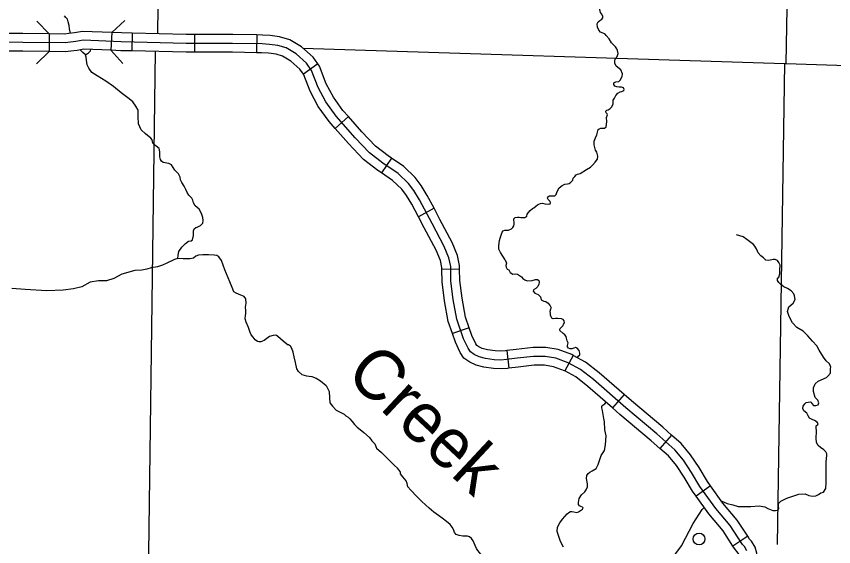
# Model space of a CAD drawing. Extents: x 1369979 to 1371646, y 379997 to 381064.
# Drawn here: x 1370592.6 to 1370673.6, y 380189.4 to 380241.9 of the extents above; entities that cross this region are included whole.
import ezdxf

# ---------------------------------------------------------------- set-up
doc = ezdxf.new("R2010")
doc.units = 0
doc.layers.add('R_Border Notes', color=7, linetype='Continuous')

msp = doc.modelspace()

# ---------------------------------------------------------------- linework, layer by layer
at = {"layer": 'R_Border Notes'}
for p, q in [((1370604.087, 380240.247), (1370604.044, 380238.489)), ((1370610.252, 380240.117), (1370610.252, 380238.359)), ((1370616.454, 380240.074), (1370616.423, 380238.316)), ((1370622.485, 380237.214), (1370621.054, 380236.193)), ((1370625.518, 380231.985), (1370624.205, 380230.817)), ((1370629.795, 380227.863), (1370628.813, 380226.405)), ((1370634.006, 380222.902), (1370632.455, 380222.075)), ((1370636.545, 380216.871), (1370634.787, 380216.839)), ((1370637.487, 380211.071), (1370635.828, 380210.489)), ((1370641.21, 380208.808), (1370641.428, 380207.064)), ((1370647.801, 380208.334), (1370646.963, 380206.789)), ((1370652.845, 380204.465), (1370651.691, 380203.139)), ((1370657.556, 380200.444), (1370656.392, 380199.127)), ((1370661.419, 380195.407), (1370659.988, 380194.386)), ((1370665.116, 380190.412), (1370663.645, 380189.449))]:
    msp.add_line(p, q, dxfattribs=at)
for points in [[(1370607.61, 380300.722), (1370606.969, 380269.654), (1370606.596, 380240.186)], [(1370670.024, 380299.56), (1370668.871, 380237.248)], [(1370650.198, 380241.187), (1370650.272, 380241.375), (1370650.455, 380241.522), (1370650.632, 380241.632), (1370650.749, 380241.787), (1370650.749, 380241.949), (1370650.61, 380242.177), (1370650.514, 380242.302), (1370650.367, 380242.869), (1370650.33, 380243.163), (1370650.316, 380243.487), (1370650.176, 380244.546)], [(1370597.953, 380240.24), (1370597.88, 380240.679), (1370597.843, 380241.01), (1370597.733, 380241.371), (1370597.682, 380241.628), (1370597.52, 380241.79), (1370597.358, 380241.974)], [(1370594.625, 380241.443), (1370595.856, 380240.189)], [(1370602.058, 380240.312), (1370603.36, 380241.494)], [(1370651.609, 380239.304), (1370651.359, 380239.694), (1370651.087, 380240.032), (1370650.977, 380240.143), (1370650.838, 380240.223), (1370650.668, 380240.282), (1370650.529, 380240.363), (1370650.352, 380240.54), (1370650.213, 380240.834), (1370650.198, 380241.187)], [(1370595.856, 380240.189), (1370593.247, 380240.221), (1370591.723, 380240.236)], [(1370595.856, 380240.189), (1370595.839, 380238.431)], [(1370597.791, 380240.22), (1370597.379, 380240.17), (1370595.856, 380240.189)], [(1370602.058, 380240.312), (1370599.152, 380240.433), (1370598.363, 380240.29), (1370597.791, 380240.22)], [(1370602.058, 380240.312), (1370601.974, 380238.556)], [(1370604.087, 380240.247), (1370603.015, 380240.273), (1370602.058, 380240.312)], [(1370610.252, 380240.117), (1370609.446, 380240.117), (1370604.087, 380240.247)], [(1370616.454, 380240.074), (1370614.05, 380240.117), (1370610.252, 380240.117)], [(1370622.485, 380237.214), (1370622.014, 380237.873), (1370620.866, 380238.905), (1370619.704, 380239.609), (1370618.693, 380239.893), (1370617.771, 380240.009), (1370616.996, 380240.064), (1370616.454, 380240.074)], [(1370599.213, 380239.55), (1370598.495, 380239.42), (1370597.427, 380239.29), (1370593.237, 380239.342), (1370587.98, 380239.394), (1370583.348, 380239.394), (1370576.087, 380239.316), (1370571.533, 380239.29)], [(1370665.035, 380188.98), (1370664.775, 380189.397), (1370664.593, 380189.606), (1370663.37, 380191.473), (1370661.938, 380193.167), (1370660.377, 380195.355), (1370659.544, 380196.746), (1370658.737, 380197.971), (1370657.879, 380198.987), (1370656.109, 380200.55), (1370653.012, 380203.155), (1370649.811, 380205.942), (1370648.543, 380206.932), (1370647.294, 380207.609), (1370646.097, 380208.052), (1370645.03, 380208.235), (1370643.885, 380208.235), (1370642.245, 380208.052), (1370641.204, 380207.922), (1370640.632, 380207.87), (1370639.981, 380207.896), (1370639.122, 380208.026), (1370638.498, 380208.182), (1370638.003, 380208.417), (1370637.613, 380208.677), (1370637.379, 380209.047), (1370636.936, 380209.985), (1370636.259, 380211.913), (1370635.921, 380213.867), (1370635.687, 380215.69), (1370635.661, 380217.149), (1370635.479, 380217.983), (1370635.01, 380219.129), (1370633.813, 380221.396), (1370632.564, 380223.74), (1370631.991, 380224.665), (1370631.471, 380225.368), (1370630.456, 380226.358), (1370628.946, 380227.374), (1370627.601, 380228.39), (1370626.196, 380229.901), (1370624.296, 380232.037), (1370623.281, 380233.455), (1370622.526, 380234.861), (1370621.875, 380236.555), (1370621.355, 380237.284), (1370620.34, 380238.196), (1370619.351, 380238.795), (1370618.518, 380239.029), (1370617.685, 380239.134), (1370616.957, 380239.186), (1370614.042, 380239.238), (1370609.435, 380239.238), (1370602.986, 380239.394), (1370599.213, 380239.55)], [(1370651.98, 380237.668), (1370652.102, 380237.825), (1370652.205, 380238.038), (1370652.264, 380238.252), (1370652.212, 380238.531), (1370652.124, 380238.7), (1370651.984, 380238.906), (1370651.793, 380239.083), (1370651.609, 380239.304), (1370651.543, 380239.399)], [(1370595.834, 380238.431), (1370593.228, 380238.463), (1370591.706, 380238.478)], [(1370595.839, 380238.431), (1370594.584, 380237.2)], [(1370595.839, 380238.431), (1370595.834, 380238.431)], [(1370598.004, 380238.475), (1370597.475, 380238.41), (1370595.839, 380238.431)], [(1370601.974, 380238.556), (1370599.274, 380238.668), (1370598.626, 380238.551), (1370598.004, 380238.475)], [(1370603.795, 380233.744), (1370602.982, 380234.335), (1370602.217, 380234.983), (1370601.46, 380235.505), (1370600.615, 380236.028), (1370600.093, 380236.344), (1370599.784, 380236.771), (1370599.608, 380237.117), (1370599.564, 380237.565), (1370599.519, 380237.882), (1370599.453, 380238.099), (1370599.203, 380238.342), (1370599.056, 380238.481), (1370598.923, 380238.605)], [(1370599.453, 380238.099), (1370599.762, 380238.295), (1370599.946, 380238.487), (1370599.968, 380238.64)], [(1370604.044, 380238.489), (1370602.958, 380238.516), (1370601.974, 380238.556)], [(1370603.156, 380237.255), (1370601.974, 380238.556)], [(1370610.252, 380238.359), (1370609.425, 380238.359), (1370604.044, 380238.489)], [(1370606.377, 380238.433), (1370605.559, 380178.814)], [(1370616.423, 380238.316), (1370614.034, 380238.359), (1370610.252, 380238.359)], [(1370621.054, 380236.193), (1370620.696, 380236.695), (1370619.814, 380237.487), (1370618.998, 380237.981), (1370618.344, 380238.166), (1370617.599, 380238.259), (1370616.917, 380238.307), (1370616.423, 380238.316)], [(1370621.017, 380238.769), (1370668.758, 380237.252), (1370668.871, 380237.248), (1370730.521, 380235.229), (1370730.683, 380235.223), (1370792.292, 380234.546), (1370792.765, 380234.537), (1370854.39, 380233.44), (1370854.696, 380233.431), (1370866.771, 380233.075)], [(1370652.024, 380234.073), (1370652.23, 380234.32), (1370652.472, 380234.446), (1370652.619, 380234.482), (1370652.81, 380234.578), (1370652.869, 380234.688), (1370652.781, 380234.85), (1370652.59, 380234.902), (1370652.362, 380234.909), (1370652.119, 380234.931), (1370651.921, 380235.012), (1370651.833, 380235.181), (1370651.848, 380235.328), (1370652.017, 380235.424), (1370652.325, 380235.461), (1370652.472, 380235.608), (1370652.656, 380235.954), (1370652.685, 380236.226), (1370652.538, 380236.616), (1370652.072, 380236.997), (1370651.921, 380237.293), (1370651.936, 380237.528), (1370651.98, 380237.668)], [(1370625.518, 380231.985), (1370624.983, 380232.587), (1370624.028, 380233.92), (1370623.327, 380235.228), (1370622.656, 380236.974), (1370622.485, 380237.214)], [(1370668.758, 380237.252), (1370668.017, 380189.594)], [(1370624.205, 380230.817), (1370623.608, 380231.488), (1370622.533, 380232.989), (1370621.725, 380234.494), (1370621.095, 380236.135), (1370621.054, 380236.193)], [(1370605.926, 380229.851), (1370605.397, 380230.272), (1370604.971, 380230.676), (1370604.714, 380231.265), (1370604.677, 380232.001), (1370604.677, 380232.633), (1370604.449, 380233.038), (1370604.14, 380233.443), (1370603.795, 380233.744)], [(1370651.215, 380232.169), (1370651.179, 380232.263), (1370651.076, 380232.374), (1370651.039, 380232.433), (1370651.032, 380232.513), (1370651.142, 380232.624), (1370651.274, 380232.661), (1370651.473, 380232.793), (1370651.649, 380232.955), (1370651.774, 380233.257), (1370651.781, 380233.396), (1370651.781, 380233.617), (1370651.906, 380233.823), (1370652.024, 380234.073)], [(1370629.795, 380227.863), (1370629.457, 380228.09), (1370628.192, 380229.045), (1370626.846, 380230.493), (1370625.518, 380231.985)], [(1370649.892, 380229.553), (1370650.002, 380229.899), (1370650.157, 380230.186), (1370650.289, 380230.708), (1370650.377, 380230.774), (1370650.546, 380230.826), (1370650.679, 380230.826), (1370650.921, 380230.855), (1370651.061, 380230.988), (1370651.112, 380231.201), (1370651.134, 380231.51), (1370651.12, 380231.885), (1370651.215, 380232.169)], [(1370628.813, 380226.405), (1370628.436, 380226.658), (1370627.01, 380227.735), (1370625.545, 380229.31), (1370624.205, 380230.817)], [(1370607.97, 380227.198), (1370607.72, 380227.334), (1370607.169, 380227.437), (1370606.985, 380227.57), (1370606.875, 380227.732), (1370606.831, 380228.004), (1370606.831, 380228.497), (1370606.772, 380228.813), (1370606.456, 380229.049), (1370606.301, 380229.181), (1370606.132, 380229.373), (1370606.051, 380229.674), (1370605.926, 380229.851)], [(1370650.002, 380228.673), (1370649.892, 380229.207), (1370649.892, 380229.553)], [(1370649.708, 380227.176), (1370649.973, 380227.466), (1370650.208, 380227.783), (1370650.238, 380228.062), (1370650.135, 380228.459), (1370650.002, 380228.673)], [(1370634.006, 380222.902), (1370633.326, 380224.179), (1370632.72, 380225.159), (1370632.135, 380225.948), (1370631.013, 380227.043), (1370629.795, 380227.863)], [(1370610.734, 380222.826), (1370610.337, 380223.137), (1370610.175, 380223.453), (1370610.109, 380223.711), (1370609.984, 380223.924), (1370609.712, 380224.204), (1370609.543, 380224.461), (1370609.389, 380224.756), (1370609.234, 380225.094), (1370608.992, 380225.462), (1370608.867, 380225.727), (1370608.845, 380225.977), (1370608.668, 380226.33), (1370608.315, 380226.669), (1370607.97, 380227.198)], [(1370644.991, 380223.347), (1370645.371, 380223.313), (1370645.511, 380223.357), (1370645.548, 380223.453), (1370645.518, 380223.592), (1370645.32, 380223.784), (1370645.247, 380223.894), (1370645.291, 380224.041), (1370645.452, 380224.129), (1370645.688, 380224.129), (1370645.79, 380224.144), (1370645.982, 380224.152), (1370646.107, 380224.277), (1370646.232, 380224.578), (1370646.408, 380224.939), (1370646.709, 380225.174), (1370646.967, 380225.292), (1370647.239, 380225.314), (1370647.415, 380225.351), (1370647.569, 380225.498), (1370647.76, 380225.697), (1370647.819, 380225.895), (1370647.959, 380226.065), (1370648.106, 380226.204), (1370648.246, 380226.285), (1370648.496, 380226.337), (1370649.113, 380226.764), (1370649.51, 380226.97), (1370649.708, 380227.176)], [(1370632.455, 380222.075), (1370631.802, 380223.302), (1370631.263, 380224.171), (1370630.807, 380224.789), (1370629.899, 380225.674), (1370628.813, 380226.405)], [(1370636.545, 380216.871), (1370636.538, 380217.252), (1370636.321, 380218.245), (1370635.808, 380219.501), (1370634.59, 380221.807), (1370634.006, 380222.902)], [(1370641.381, 380220.755), (1370641.705, 380220.883), (1370641.815, 380221.008), (1370641.911, 380221.155), (1370641.97, 380221.317), (1370641.955, 380221.53), (1370641.911, 380221.714), (1370641.933, 380221.846), (1370642.065, 380221.979), (1370642.278, 380222.023), (1370642.433, 380222.016), (1370642.631, 380221.994), (1370642.83, 380221.986), (1370643.021, 380222.001), (1370643.197, 380222.119), (1370643.241, 380222.317), (1370643.359, 380222.487), (1370643.535, 380222.7), (1370643.763, 380222.884), (1370643.895, 380222.965), (1370644.087, 380223.112), (1370644.278, 380223.237), (1370644.41, 380223.318), (1370644.557, 380223.392), (1370644.755, 380223.414), (1370644.991, 380223.347)], [(1370608.61, 380217.931), (1370608.639, 380218.265), (1370608.698, 380218.625), (1370609.006, 380219.067), (1370609.367, 380219.42), (1370609.668, 380219.655), (1370609.947, 380219.692), (1370610.05, 380219.788), (1370610.146, 380220.2), (1370610.168, 380220.509), (1370610.153, 380220.671), (1370610.219, 380220.869), (1370610.396, 380220.994), (1370610.528, 380221.046), (1370610.866, 380221.193), (1370611.094, 380221.421), (1370611.116, 380221.701), (1370611.087, 380221.98), (1370610.962, 380222.378), (1370610.734, 380222.826)], [(1370634.787, 380216.839), (1370634.784, 380217.047), (1370634.636, 380217.721), (1370634.213, 380218.757), (1370633.037, 380220.984), (1370632.455, 380222.075)], [(1370641.064, 380217.793), (1370640.838, 380218.172), (1370640.602, 380218.533), (1370640.448, 380218.849), (1370640.441, 380219.209), (1370640.499, 380219.717), (1370640.558, 380219.938), (1370640.749, 380220.549), (1370640.874, 380220.666), (1370641.029, 380220.74), (1370641.381, 380220.755)], [(1370668.184, 380216.096), (1370668.304, 380216.399), (1370668.304, 380216.782), (1370668.319, 380217.267), (1370668.202, 380217.547), (1370668.055, 380217.724), (1370667.834, 380217.827), (1370667.628, 380217.841), (1370667.202, 380217.738), (1370666.908, 380217.768), (1370666.673, 380217.988), (1370666.408, 380218.194), (1370666.143, 380218.504), (1370666.011, 380218.827), (1370665.82, 380219.151), (1370665.673, 380219.328), (1370665.423, 380219.519), (1370665.026, 380219.813), (1370664.658, 380220.078), (1370664.012, 380220.284)], [(1370613.268, 380216.798), (1370612.937, 380217.74), (1370612.672, 380218.086), (1370612.481, 380218.218), (1370612.195, 380218.255), (1370611.665, 380218.306), (1370611.077, 380218.292), (1370610.673, 380218.262), (1370610.401, 380218.159), (1370610.158, 380217.975), (1370609.813, 380217.902), (1370609.137, 380217.902), (1370608.61, 380217.931), (1370608.279, 380217.828), (1370607.522, 380217.475), (1370607.103, 380217.269), (1370606.595, 380217.1), (1370605.963, 380216.997), (1370605.544, 380216.879), (1370605.044, 380216.769), (1370604.346, 380216.732)], [(1370641.064, 380217.793), (1370641.189, 380217.484), (1370641.123, 380217.234), (1370641.145, 380217.072), (1370641.255, 380216.866), (1370641.409, 380216.8), (1370641.564, 380216.542), (1370641.806, 380216.395), (1370642.078, 380216.403), (1370642.292, 380216.373), (1370642.688, 380216.123), (1370642.799, 380215.954), (1370642.997, 380215.814), (1370643.254, 380215.733), (1370643.747, 380215.755), (1370644.063, 380215.858), (1370644.262, 380215.858), (1370644.401, 380215.755), (1370644.423, 380215.571), (1370644.401, 380215.402), (1370644.313, 380215.174), (1370644.092, 380214.953), (1370643.857, 380214.828), (1370643.835, 380214.703), (1370644.004, 380214.512), (1370644.342, 380214.379), (1370644.57, 380214.144), (1370644.636, 380213.835)], [(1370604.346, 380216.732), (1370603.048, 380216.381), (1370602.257, 380215.963), (1370601.522, 380215.718), (1370600.748, 380215.735), (1370599.928, 380215.591), (1370599.093, 380215.137), (1370598.265, 380214.943), (1370597.247, 380214.781), (1370595.606, 380214.738), (1370593.489, 380214.853), (1370592.136, 380214.968)], [(1370615.377, 380211.611), (1370615.275, 380211.969), (1370615.333, 380212.271), (1370615.348, 380212.455), (1370615.363, 380212.771), (1370615.326, 380213.102), (1370615.377, 380213.5), (1370615.341, 380213.941), (1370615.179, 380214.184), (1370614.87, 380214.309), (1370614.385, 380214.486), (1370614.15, 380214.642), (1370613.988, 380215.047), (1370613.76, 380215.606), (1370613.268, 380216.798)], [(1370635.828, 380210.488), (1370635.406, 380211.691), (1370635.052, 380213.736), (1370634.809, 380215.626), (1370634.787, 380216.839)], [(1370637.487, 380211.071), (1370637.113, 380212.135), (1370636.79, 380213.998), (1370636.565, 380215.754), (1370636.545, 380216.871)], [(1370670.61, 380210.719), (1370669.963, 380211.108), (1370669.536, 380211.549), (1370669.228, 380212.182), (1370669.066, 380212.682), (1370669.184, 380213.138), (1370669.625, 380213.506), (1370669.801, 380213.859), (1370669.757, 380214.227), (1370669.669, 380214.448), (1370669.419, 380214.742), (1370669.066, 380214.948), (1370668.698, 380215.14), (1370668.346, 380215.404), (1370668.199, 380215.566), (1370668.052, 380215.743), (1370668.052, 380215.875), (1370668.066, 380215.978), (1370668.184, 380216.096)], [(1370644.636, 380213.835), (1370644.901, 380213.698), (1370645.092, 380213.683), (1370645.335, 380213.514), (1370645.511, 380213.256), (1370645.607, 380213.058), (1370645.57, 380212.903), (1370645.474, 380212.675), (1370645.518, 380212.513), (1370645.526, 380212.366)], [(1370618.383, 380210.308), (1370618.243, 380210.33), (1370618.052, 380210.308), (1370617.685, 380210.191), (1370617.178, 380209.801), (1370616.832, 380209.661), (1370616.648, 380209.668), (1370616.501, 380209.72), (1370616.288, 380209.867), (1370616.082, 380210.124), (1370615.891, 380210.382), (1370615.796, 380210.617), (1370615.605, 380211.088), (1370615.377, 380211.611)], [(1370646.803, 380210.511), (1370646.487, 380210.787), (1370646.479, 380210.868), (1370646.523, 380211.001), (1370646.714, 380211.207), (1370646.825, 380211.31), (1370646.861, 380211.413), (1370646.935, 380211.552), (1370646.913, 380211.758), (1370646.803, 380211.891), (1370646.656, 380211.95), (1370646.273, 380211.987), (1370646.06, 380211.972), (1370645.825, 380211.957), (1370645.678, 380212.031), (1370645.612, 380212.148), (1370645.56, 380212.318)], [(1370641.21, 380208.808), (1370641.11, 380208.796), (1370640.609, 380208.75), (1370640.065, 380208.772), (1370639.295, 380208.889), (1370638.795, 380209.014), (1370638.438, 380209.184), (1370638.256, 380209.305), (1370638.15, 380209.472), (1370637.75, 380210.319), (1370637.487, 380211.071)], [(1370619.533, 380209.363), (1370619.42, 380209.462), (1370619.052, 380209.756), (1370618.795, 380209.962), (1370618.523, 380210.213), (1370618.383, 380210.308)], [(1370641.428, 380207.064), (1370641.299, 380207.048), (1370640.654, 380206.989), (1370639.897, 380207.02), (1370638.949, 380207.163), (1370638.2, 380207.351), (1370637.569, 380207.65), (1370636.97, 380208.05), (1370636.607, 380208.623), (1370636.122, 380209.651), (1370635.828, 380210.488)], [(1370648.178, 380208.13), (1370648.273, 380208.208), (1370648.449, 380208.399), (1370648.457, 380208.568), (1370648.383, 380208.818), (1370648.185, 380209.046), (1370648.067, 380209.127), (1370648.023, 380209.127), (1370647.854, 380209.046), (1370647.67, 380208.973), (1370647.501, 380208.98), (1370647.339, 380209.046), (1370647.244, 380209.179), (1370647.251, 380209.311), (1370647.295, 380209.569), (1370647.207, 380209.768), (1370647.163, 380209.907), (1370647.156, 380210.04), (1370647.097, 380210.194), (1370646.972, 380210.356), (1370646.803, 380210.511)], [(1370672.095, 380205.767), (1370672.903, 380206.143), (1370673.05, 380206.275), (1370673.315, 380206.569), (1370673.329, 380206.746), (1370673.3, 380207.04), (1370673.344, 380207.173), (1370673.212, 380207.482), (1370672.888, 380207.805), (1370672.609, 380208.173), (1370672.197, 380208.85), (1370671.948, 380209.277), (1370671.521, 380209.733), (1370671.065, 380210.263), (1370670.771, 380210.572), (1370670.61, 380210.719)], [(1370620.138, 380208.181), (1370620.044, 380208.668), (1370619.897, 380209.028), (1370619.765, 380209.234), (1370619.567, 380209.396), (1370619.42, 380209.462)], [(1370647.801, 380208.334), (1370647.658, 380208.412), (1370646.325, 380208.905), (1370645.105, 380209.113), (1370643.836, 380209.113), (1370642.142, 380208.925), (1370641.21, 380208.808)], [(1370652.845, 380204.465), (1370650.37, 380206.62), (1370649.027, 380207.67), (1370647.801, 380208.334)], [(1370620.265, 380207.623), (1370620.138, 380208.181)], [(1370620.919, 380206.453), (1370620.581, 380206.74), (1370620.397, 380207.012), (1370620.265, 380207.623)], [(1370646.963, 380206.789), (1370646.93, 380206.807), (1370645.869, 380207.2), (1370644.955, 380207.356), (1370643.934, 380207.356), (1370642.348, 380207.179), (1370641.428, 380207.064)], [(1370651.691, 380203.139), (1370649.251, 380205.264), (1370648.06, 380206.194), (1370646.963, 380206.789)], [(1370620.919, 380206.453), (1370621.372, 380206.304), (1370621.879, 380206.245), (1370622.313, 380206.083), (1370622.769, 380205.811), (1370623.311, 380205.363), (1370623.598, 380204.767), (1370623.639, 380204.13), (1370623.665, 380203.618), (1370623.937, 380203.302), (1370624.32, 380202.919), (1370624.82, 380202.639), (1370625.092, 380202.522), (1370625.268, 380202.358), (1370625.511, 380202.226), (1370625.658, 380202.057), (1370625.891, 380201.799), (1370626.127, 380201.498), (1370626.391, 380201.218), (1370626.693, 380200.99), (1370627.045, 380200.703), (1370627.603, 380200.213), (1370627.839, 380199.882), (1370628.126, 380199.57)], [(1370671.903, 380201.372), (1370672.05, 380201.5), (1370672.08, 380201.603), (1370671.977, 380201.735), (1370671.742, 380201.897), (1370671.506, 380201.986), (1370671.242, 380202.103), (1370671.11, 380202.339), (1370670.977, 380202.618), (1370670.668, 380202.839), (1370670.566, 380203.06), (1370670.61, 380203.295), (1370670.757, 380203.545), (1370670.918, 380203.663), (1370671.286, 380203.737), (1370671.404, 380203.693), (1370671.477, 380203.575), (1370671.639, 380203.369), (1370671.859, 380203.369), (1370672.095, 380203.442), (1370672.153, 380203.619), (1370672.05, 380203.913), (1370671.786, 380204.178), (1370671.624, 380204.767), (1370671.624, 380205.105), (1370671.8, 380205.502), (1370672.095, 380205.767)], [(1370657.556, 380200.444), (1370656.683, 380201.215), (1370653.583, 380203.822), (1370652.845, 380204.465)], [(1370650.897, 380201.768), (1370650.831, 380202.072), (1370650.765, 380202.492), (1370650.721, 380202.889), (1370650.654, 380203.146), (1370650.654, 380203.271), (1370650.75, 380203.397), (1370650.956, 380203.551), (1370651.066, 380203.684)], [(1370656.392, 380199.127), (1370655.535, 380199.884), (1370652.44, 380202.487), (1370651.691, 380203.139)], [(1370650.295, 380197.513), (1370650.574, 380198.42), (1370650.897, 380198.92), (1370651, 380199.479), (1370651.059, 380200.355), (1370650.956, 380200.944), (1370650.897, 380201.768)], [(1370672.627, 380194.772), (1370672.859, 380195.162), (1370672.874, 380195.736), (1370672.874, 380196.913), (1370672.874, 380197.796), (1370672.947, 380198.429), (1370672.947, 380198.576), (1370672.859, 380198.782), (1370672.638, 380198.988), (1370672.315, 380199.194), (1370672.095, 380199.4), (1370671.933, 380199.709), (1370671.903, 380200.136), (1370671.918, 380200.783), (1370671.889, 380201.225), (1370671.903, 380201.372)], [(1370661.419, 380195.407), (1370661.113, 380195.837), (1370660.288, 380197.214), (1370659.442, 380198.498), (1370658.508, 380199.603), (1370657.556, 380200.444)], [(1370628.126, 380199.57), (1370628.316, 380199.139), (1370628.808, 380198.712), (1370629.631, 380197.873), (1370630.087, 380197.424), (1370630.378, 380197.151)], [(1370659.988, 380194.386), (1370659.641, 380194.873), (1370658.8, 380196.278), (1370658.032, 380197.443), (1370657.249, 380198.37), (1370656.392, 380199.127)], [(1370632.796, 380193.852), (1370632.311, 380194.363), (1370631.709, 380194.988), (1370631.415, 380195.326), (1370631.334, 380195.643), (1370631.238, 380195.922), (1370630.929, 380196.312), (1370630.679, 380196.614), (1370630.672, 380196.724), (1370630.643, 380196.827), (1370630.554, 380196.967), (1370630.378, 380197.151)], [(1370648.546, 380192.98), (1370648.744, 380193.114), (1370648.781, 380193.217), (1370648.722, 380193.298), (1370648.56, 380193.371), (1370648.435, 380193.415), (1370648.347, 380193.555), (1370648.318, 380193.768), (1370648.413, 380194.173), (1370648.634, 380194.534), (1370648.95, 380194.806), (1370649.09, 380195.012), (1370649.214, 380195.328), (1370649.222, 380195.608), (1370649.134, 380196.123), (1370649.163, 380196.432), (1370649.288, 380196.638), (1370649.442, 380196.778), (1370649.692, 380196.903), (1370650.067, 380197.138), (1370650.295, 380197.513)], [(1370665.116, 380190.412), (1370664.076, 380192), (1370662.633, 380193.707), (1370661.419, 380195.407)], [(1370665.411, 380193.38), (1370666.246, 380193.418), (1370666.79, 380193.33), (1370667.099, 380193.183), (1370667.613, 380192.977), (1370667.863, 380192.962), (1370668.099, 380192.992), (1370668.187, 380193.153), (1370668.172, 380193.389), (1370668.157, 380193.654), (1370668.378, 380193.904), (1370668.981, 380194.183), (1370670.172, 380194.581), (1370670.789, 380194.61), (1370671.157, 380194.463), (1370671.539, 380194.375), (1370671.848, 380194.419), (1370672.112, 380194.551), (1370672.362, 380194.713), (1370672.627, 380194.772)], [(1370637.903, 380189.972), (1370637.714, 380190.181), (1370637.538, 380190.357), (1370637.317, 380190.416), (1370636.861, 380190.416), (1370636.509, 380190.504), (1370636.193, 380190.607), (1370636.038, 380190.791), (1370635.965, 380191.005), (1370635.796, 380191.321), (1370635.604, 380191.586), (1370635.259, 380191.865), (1370634.811, 380192.211), (1370634.458, 380192.484), (1370633.995, 380192.793), (1370633.524, 380193.197), (1370632.796, 380193.852)], [(1370663.645, 380189.449), (1370662.664, 380190.947), (1370661.244, 380192.627), (1370659.988, 380194.386)], [(1370662.485, 380193.915), (1370663.074, 380193.674), (1370663.618, 380193.527), (1370664.162, 380193.38), (1370664.823, 380193.365), (1370665.411, 380193.38)], [(1370646.83, 380189.33), (1370646.561, 380189.904), (1370646.208, 380190.89), (1370646.259, 380191.332), (1370646.465, 380191.751), (1370646.752, 380192.104), (1370647.193, 380192.641), (1370647.362, 380192.774), (1370647.531, 380192.877), (1370647.656, 380192.884), (1370647.869, 380192.825), (1370648.156, 380192.781), (1370648.318, 380192.825), (1370648.546, 380192.98)], [(1370656.814, 380186.945), (1370657.428, 380187.965), (1370658.546, 380189.466), (1370659.707, 380191.673), (1370660.604, 380193.071), (1370660.79, 380193.264)], [(1370640.16, 380185.997), (1370640.072, 380186.227), (1370639.991, 380186.448), (1370639.888, 380186.647), (1370639.66, 380186.875), (1370639.535, 380187.051), (1370639.425, 380187.331), (1370639.307, 380187.669), (1370639.285, 380187.898), (1370639.307, 380188.074), (1370639.241, 380188.192), (1370639.138, 380188.324), (1370639.028, 380188.398), (1370638.778, 380188.523), (1370638.623, 380188.677), (1370638.528, 380188.825), (1370638.359, 380189.016), (1370638.219, 380189.2), (1370638.094, 380189.509), (1370637.903, 380189.972)], [(1370667.424, 380184.654), (1370666.694, 380186.116), (1370666.237, 380187.214), (1370666.166, 380187.999), (1370665.996, 380188.737), (1370665.858, 380189.323), (1370665.483, 380189.922), (1370665.295, 380190.138), (1370665.116, 380190.412)], [(1370665.851, 380183.869), (1370665.094, 380185.384), (1370664.511, 380186.787), (1370664.426, 380187.721), (1370664.283, 380188.338), (1370664.213, 380188.638), (1370664.067, 380188.872), (1370663.891, 380189.073), (1370663.645, 380189.449)]]:
    msp.add_lwpolyline(points, dxfattribs=at)
msp.add_circle((1370660.287, 380190.147), 0.586, dxfattribs=at)

# ---------------------------------------------------------------- texts
msp.add_text('Creek', height=4.95, rotation=316.91403, dxfattribs=at).set_placement((1370625.078, 380206.291))

doc.saveas('drawing.dxf')
